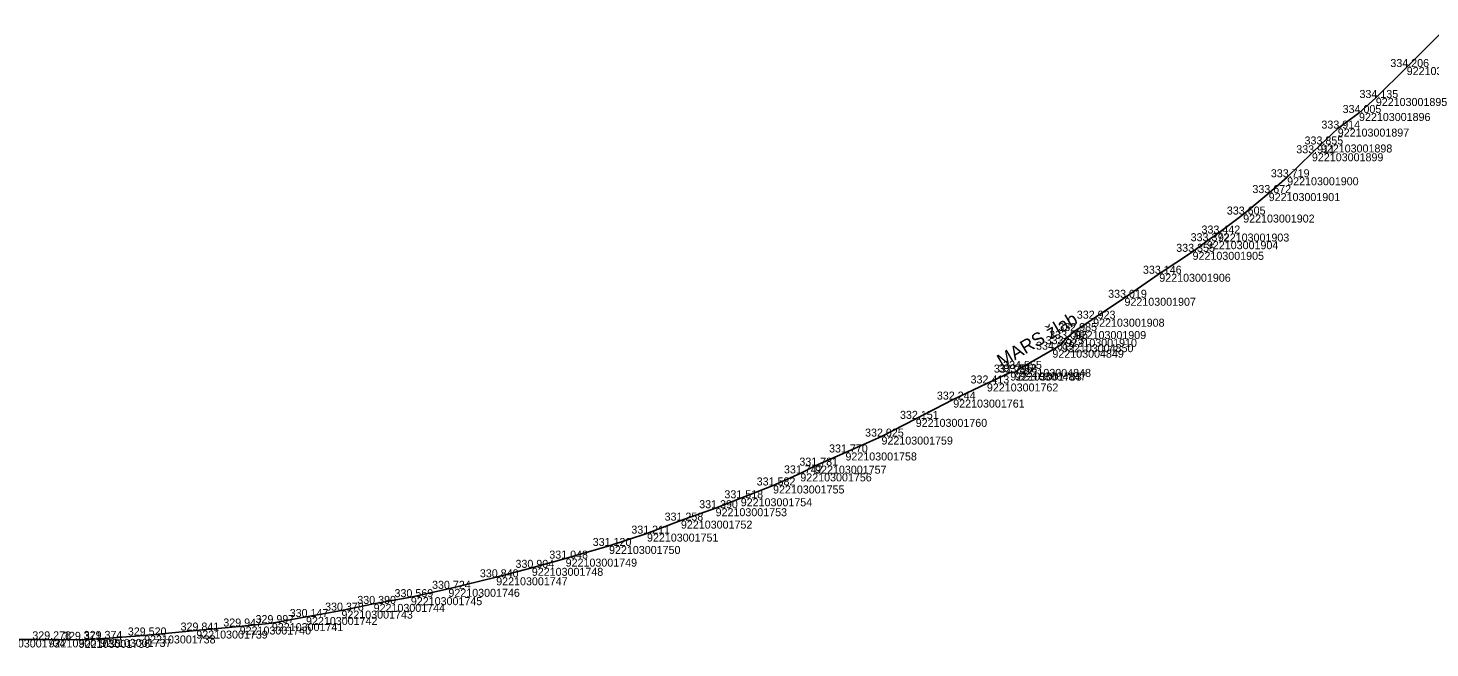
# Model space of a CAD drawing. Extents: x -771047 to -756200, y -1053876 to -1046520.
# Drawn here: x -759698.8 to -759488.6, y -1049533.4 to -1049440.4 of the extents above; entities that cross this region are included whole.
import ezdxf

# ---------------------------------------------------------------- set-up
doc = ezdxf.new("R2010")
doc.units = 0
for name, color, linetype in [('Vrstva 32', 7, 'Continuous'), ('Vrstva 33', 7, 'Continuous'), ('Vrstva 60', 7, 'Continuous'), ('Vrstva 61', 7, 'Continuous')]:
    doc.layers.add(name, color=color, linetype=linetype)

msp = doc.modelspace()

# ---------------------------------------------------------------- linework, layer by layer
at = {"layer": 'Vrstva 32'}
for points in [[(-759486.2, -1049440.4), (-759492.08, -1049446.25), (-759496.71, -1049450.89), (-759499.23, -1049453.14), (-759502.42, -1049455.48), (-759504.95, -1049457.86), (-759506.29, -1049459.18), (-759510, -1049462.78), (-759512.77, -1049465.15), (-759516.6, -1049468.37), (-759520.4, -1049471.22), (-759522.04, -1049472.37), (-759524.19, -1049473.96), (-759529.18, -1049477.25), (-759534.4, -1049480.85), (-759539.1, -1049483.99), (-759541.86, -1049485.84), (-759543.24, -1049487), (-759543.77, -1049487.81)], [(-759550.84, -1049492.05), (-759550.13, -1049491.52), (-759545.21, -1049488.64), (-759543.77, -1049487.81)], [(-759703.91, -1049532.09), (-759695.72, -1049532.08), (-759691.21, -1049532.15), (-759688.02, -1049532.01), (-759681.4, -1049531.49), (-759673.58, -1049530.76), (-759667.08, -1049530.15), (-759662.25, -1049529.64), (-759657.13, -1049528.72), (-759651.82, -1049527.77), (-759646.99, -1049526.76), (-759641.41, -1049525.75), (-759635.78, -1049524.5), (-759628.61, -1049522.77), (-759623.27, -1049521.35), (-759618.2, -1049519.97), (-759611.69, -1049518.07), (-759606, -1049516.22), (-759600.91, -1049514.27), (-759595.71, -1049512.41), (-759591.94, -1049510.92), (-759587.1, -1049509), (-759583.01, -1049507.19), (-759580.79, -1049506.03), (-759576.24, -1049504.05), (-759570.84, -1049501.67), (-759565.7, -1049499.01), (-759560.08, -1049496.12), (-759555.03, -1049493.7), (-759551.52, -1049492.07), (-759550.84, -1049492.05)]]:
    msp.add_lwpolyline(points, dxfattribs=at)
at = {"layer": 'Vrstva 33'}
msp.add_lwpolyline([(-759550.84, -1049492.05), (-759550.13, -1049491.52), (-759545.21, -1049488.64), (-759543.77, -1049487.81)], dxfattribs=at)
at = {"layer": 'Vrstva 60'}
for p, q in [((-759492.08, -1049446.25), (-759492.08, -1049446.25)), ((-759496.71, -1049450.89), (-759496.71, -1049450.89)), ((-759499.23, -1049453.14), (-759499.23, -1049453.14)), ((-759502.42, -1049455.48), (-759502.42, -1049455.48)), ((-759504.95, -1049457.86), (-759504.95, -1049457.86)), ((-759506.29, -1049459.18), (-759506.29, -1049459.18)), ((-759510, -1049462.78), (-759510, -1049462.78)), ((-759512.77, -1049465.15), (-759512.77, -1049465.15)), ((-759516.6, -1049468.37), (-759516.6, -1049468.37)), ((-759522.04, -1049472.37), (-759522.04, -1049472.37)), ((-759520.4, -1049471.22), (-759520.4, -1049471.22)), ((-759524.19, -1049473.96), (-759524.19, -1049473.96)), ((-759529.18, -1049477.25), (-759529.18, -1049477.25)), ((-759534.4, -1049480.85), (-759534.4, -1049480.85)), ((-759539.1, -1049483.99), (-759539.1, -1049483.99)), ((-759543.24, -1049487), (-759543.24, -1049487)), ((-759541.86, -1049485.84), (-759541.86, -1049485.84)), ((-759545.21, -1049488.64), (-759545.21, -1049488.64)), ((-759543.77, -1049487.81), (-759543.77, -1049487.81)), ((-759550.13, -1049491.52), (-759550.13, -1049491.52)), ((-759555.03, -1049493.7), (-759555.03, -1049493.7)), ((-759551.52, -1049492.07), (-759551.52, -1049492.07)), ((-759550.84, -1049492.05), (-759550.84, -1049492.05)), ((-759560.08, -1049496.12), (-759560.08, -1049496.12)), ((-759565.7, -1049499.01), (-759565.7, -1049499.01)), ((-759570.84, -1049501.67), (-759570.84, -1049501.67)), ((-759576.24, -1049504.05), (-759576.24, -1049504.05)), ((-759580.79, -1049506.03), (-759580.79, -1049506.03)), ((-759583.01, -1049507.19), (-759583.01, -1049507.19)), ((-759587.1, -1049509), (-759587.1, -1049509)), ((-759595.71, -1049512.41), (-759595.71, -1049512.41)), ((-759591.94, -1049510.92), (-759591.94, -1049510.92)), ((-759600.91, -1049514.27), (-759600.91, -1049514.27)), ((-759606, -1049516.22), (-759606, -1049516.22)), ((-759611.69, -1049518.07), (-759611.69, -1049518.07)), ((-759618.2, -1049519.97), (-759618.2, -1049519.97)), ((-759628.61, -1049522.77), (-759628.61, -1049522.77)), ((-759623.27, -1049521.35), (-759623.27, -1049521.35)), ((-759635.78, -1049524.5), (-759635.78, -1049524.5)), ((-759646.99, -1049526.76), (-759646.99, -1049526.76)), ((-759641.41, -1049525.75), (-759641.41, -1049525.75)), ((-759657.13, -1049528.72), (-759657.13, -1049528.72)), ((-759651.82, -1049527.77), (-759651.82, -1049527.77)), ((-759681.4, -1049531.49), (-759681.4, -1049531.49)), ((-759673.58, -1049530.76), (-759673.58, -1049530.76)), ((-759667.08, -1049530.15), (-759667.08, -1049530.15)), ((-759662.25, -1049529.64), (-759662.25, -1049529.64)), ((-759695.72, -1049532.08), (-759695.72, -1049532.08)), ((-759691.21, -1049532.15), (-759691.21, -1049532.15)), ((-759688.02, -1049532.01), (-759688.02, -1049532.01))]:
    msp.add_line(p, q, dxfattribs=at)

# ---------------------------------------------------------------- texts
at = {"layer": 'Vrstva 33'}
msp.add_text('MARS žlab', height=2, rotation=30.3382, dxfattribs=at).set_placement((-759552.77, -1049491.37))
at = {"layer": 'Vrstva 60'}
for s, p in [('922103001894', (-759492.08, -1049447.45)), ('922103001895', (-759496.71, -1049452.09)), ('922103001896', (-759499.23, -1049454.34)), ('922103001897', (-759502.42, -1049456.68)), ('922103001898', (-759504.95, -1049459.06)), ('922103001899', (-759506.29, -1049460.38)), ('922103001900', (-759510, -1049463.98)), ('922103001901', (-759512.77, -1049466.35)), ('922103001902', (-759516.6, -1049469.57)), ('922103001904', (-759522.04, -1049473.57)), ('922103001903', (-759520.4, -1049472.42)), ('922103001905', (-759524.19, -1049475.16)), ('922103001906', (-759529.18, -1049478.45)), ('922103001907', (-759534.4, -1049482.05)), ('922103001908', (-759539.1, -1049485.19)), ('922103001910', (-759543.24, -1049488.2)), ('922103001909', (-759541.86, -1049487.04)), ('922103004849', (-759545.21, -1049489.84)), ('922103004850', (-759543.77, -1049489.01)), ('922103004848', (-759550.13, -1049492.72)), ('922103001762', (-759555.03, -1049494.9)), ('922103001763', (-759551.52, -1049493.27)), ('922103004847', (-759550.84, -1049493.25)), ('922103001761', (-759560.08, -1049497.32)), ('922103001760', (-759565.7, -1049500.21)), ('922103001759', (-759570.84, -1049502.87)), ('922103001758', (-759576.24, -1049505.25)), ('922103001757', (-759580.79, -1049507.23)), ('922103001756', (-759583.01, -1049508.39)), ('922103001755', (-759587.1, -1049510.2)), ('922103001753', (-759595.71, -1049513.61)), ('922103001754', (-759591.94, -1049512.12)), ('922103001752', (-759600.91, -1049515.47)), ('922103001751', (-759606, -1049517.42)), ('922103001750', (-759611.69, -1049519.27)), ('922103001749', (-759618.2, -1049521.17)), ('922103001747', (-759628.61, -1049523.97)), ('922103001748', (-759623.27, -1049522.55)), ('922103001746', (-759635.78, -1049525.7)), ('922103001744', (-759646.99, -1049527.96)), ('922103001745', (-759641.41, -1049526.95)), ('922103001742', (-759657.13, -1049529.92)), ('922103001743', (-759651.82, -1049528.97)), ('922103001738', (-759681.4, -1049532.69)), ('922103001739', (-759673.58, -1049531.96)), ('922103001740', (-759667.08, -1049531.35)), ('922103001741', (-759662.25, -1049530.84)), ('922103001734', (-759703.91, -1049533.29)), ('922103001735', (-759695.72, -1049533.28)), ('922103001736', (-759691.21, -1049533.35)), ('922103001737', (-759688.02, -1049533.21))]:
    msp.add_text(s, height=1.2, dxfattribs=at).set_placement(p)
at = {"layer": 'Vrstva 61'}
for s, p in [('334.206', (-759494.53, -1049446.25)), ('334.135', (-759499.16, -1049450.89)), ('334.005', (-759501.69, -1049453.14)), ('333.914', (-759504.87, -1049455.48)), ('333.911', (-759508.64, -1049459.18)), ('333.855', (-759507.4, -1049457.86)), ('333.719', (-759512.45, -1049462.78)), ('333.672', (-759515.22, -1049465.15)), ('333.605', (-759519.05, -1049468.37)), ('333.442', (-759522.85, -1049471.22)), ('333.372', (-759524.48, -1049472.37)), ('333.355', (-759526.64, -1049473.96)), ('333.146', (-759531.63, -1049477.25)), ('333.019', (-759536.85, -1049480.85)), ('332.923', (-759541.55, -1049483.99)), ('332.985', (-759544.32, -1049485.84)), ('334.619', (-759547.66, -1049488.64)), ('333.573', (-759546.22, -1049487.81)), ('333.096', (-759545.69, -1049487)), ('332.795', (-759553.98, -1049492.07)), ('333.518', (-759553.3, -1049492.05)), ('334.555', (-759552.59, -1049491.52)), ('332.413', (-759557.48, -1049493.7)), ('332.244', (-759562.53, -1049496.12)), ('332.151', (-759568.06, -1049499.01)), ('332.025', (-759573.3, -1049501.67)), ('331.770', (-759578.7, -1049504.05)), ('331.742', (-759585.46, -1049507.19)), ('331.781', (-759583.15, -1049506.03)), ('331.582', (-759589.55, -1049509)), ('331.518', (-759594.39, -1049510.92)), ('331.390', (-759598.17, -1049512.41)), ('331.258', (-759603.36, -1049514.27)), ('331.120', (-759614.14, -1049518.07)), ('331.211', (-759608.35, -1049516.22)), ('331.048', (-759620.65, -1049519.97)), ('330.904', (-759625.72, -1049521.35)), ('330.840', (-759631.06, -1049522.77)), ('330.569', (-759643.86, -1049525.75)), ('330.724', (-759638.23, -1049524.5)), ('330.378', (-759654.27, -1049527.77)), ('330.390', (-759649.44, -1049526.76)), ('329.947', (-759669.53, -1049530.15)), ('329.997', (-759664.7, -1049529.64)), ('330.147', (-759659.58, -1049528.72)), ('329.278', (-759698.17, -1049532.08)), ('329.371', (-759693.57, -1049532.15)), ('329.374', (-759690.47, -1049532.01)), ('329.520', (-759683.85, -1049531.49)), ('329.841', (-759675.94, -1049530.76))]:
    msp.add_text(s, height=1.2, dxfattribs=at).set_placement(p)

doc.saveas('drawing.dxf')
